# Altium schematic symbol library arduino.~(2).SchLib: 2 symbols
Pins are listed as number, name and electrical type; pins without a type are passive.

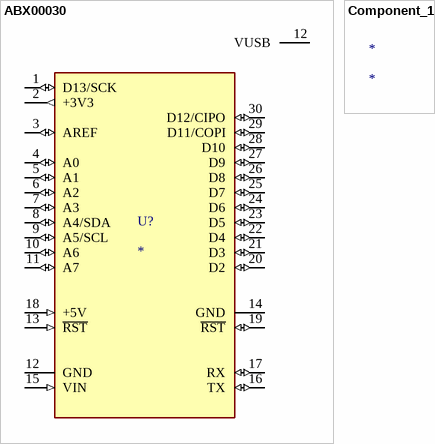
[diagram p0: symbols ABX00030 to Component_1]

## ABX00030
designator U?
NINA-B306, nRF52840 Arduino Nano 33 BLE series ARMÂ® CortexÂ®-M4F MCU 32-Bit Embedded Evaluation Board; MP: ABX00030
footprint MODULE_ABX00030
pins: 1 D13/SCK (io), 2 +3V3 (out), 3 AREF (io), 4 A0 (io), 5 A1 (io), 6 A2 (io), 7 A3 (io), 8 A4/SDA (io), 9 A5/SCL (io), 10 A6 (io), 11 A7 (io), 12 VUSB (power), 12 GND (power), 13 ~{RST} (in), 14 GND (power), 15 VIN (in), 16 TX (io), 17 RX (io), 18 +5V (in), 19 ~{RST} (io), 20 D2 (io), 21 D3 (io), 22 D4 (io), 23 D5 (io), 24 D6 (io), 25 D7 (io), 26 D8 (io), 27 D9 (io), 28 D10 (io), 29 D11/COPI (io), 30 D12/CIPO (io)

## Component_1
designator *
